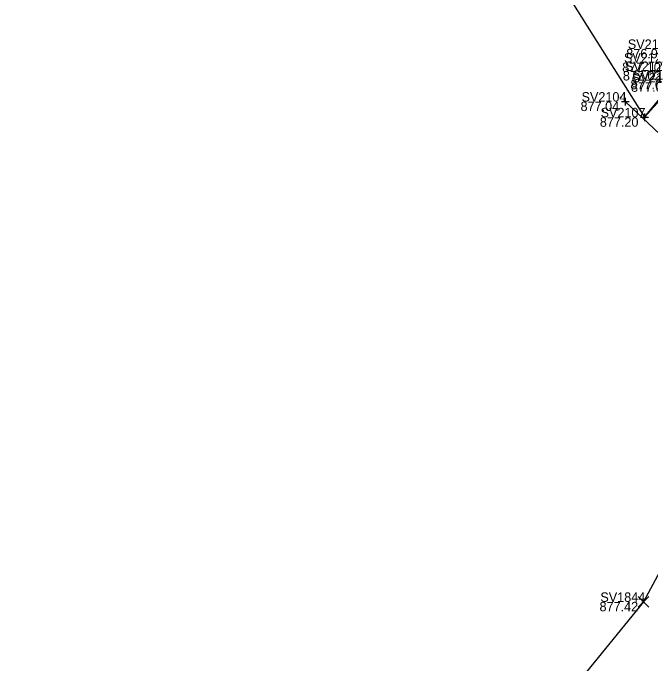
# Model space of a CAD drawing. Extents: x 1475918 to 1480402, y 379235 to 383359.
# Drawn here: x 1480006.1 to 1480087.1, y 379351.5 to 379434.1 of the extents above; entities that cross this region are included whole.
import ezdxf

# ---------------------------------------------------------------- set-up
doc = ezdxf.new("R2010")
doc.units = 0
for name, color, linetype in [('BD_X_Building', 7, 'Continuous'), ('BD_X_Porch_or_Deck', 7, 'Continuous'), ('SV_X_Random_Point', 7, 'Continuous'), ('SV_X_Shot_Marker', 7, 'Continuous'), ('SV_X_Text_Comment', 7, 'Continuous'), ('SV_X_Text_Elevation', 7, 'Continuous'), ('SV_X_Text_Name', 7, 'Continuous'), ('XS_X_Ground_Line', 7, 'Continuous')]:
    doc.layers.add(name, color=color, linetype=linetype)

msp = doc.modelspace()

# ---------------------------------------------------------------- linework, layer by layer
at = {"layer": 'BD_X_Building'}
msp.add_line((1480104.802, 379403.171), (1480083.928, 379422.85), dxfattribs=at)
at = {"layer": 'BD_X_Porch_or_Deck'}
msp.add_lwpolyline([(1480086.359, 379420.856), (1480090.342, 379425.296), (1480106.828, 379410.03), (1480102.697, 379405.586)], dxfattribs=at)
at = {"layer": 'SV_X_Random_Point'}
for p, q in [((1480085.569, 379358.641), (1480086.903, 379359.976)), ((1480085.569, 379359.976), (1480086.903, 379358.641))]:
    msp.add_line(p, q, dxfattribs=at)
at = {"layer": 'SV_X_Shot_Marker'}
for p, q in [((1480083.351, 379423.394), (1480083.315, 379423.428)), ((1480083.316, 379423.393), (1480083.35, 379423.429)), ((1480083.333, 379423.411), (1480083.333, 379423.411)), ((1480083.928, 379423.35), (1480083.928, 379422.35)), ((1480083.428, 379422.85), (1480084.428, 379422.85)), ((1480083.928, 379422.85), (1480083.928, 379422.85)), ((1480085.859, 379420.856), (1480086.859, 379420.856)), ((1480086.34, 379420.873), (1480086.378, 379420.84)), ((1480086.342, 379420.838), (1480086.376, 379420.875)), ((1480086.359, 379421.356), (1480086.359, 379420.356)), ((1480086.359, 379420.856), (1480086.359, 379420.856)), ((1480086.359, 379420.856), (1480086.359, 379420.856))]:
    msp.add_line(p, q, dxfattribs=at)
at = {"layer": 'XS_X_Ground_Line'}
msp.add_lwpolyline([(1480006.1, 379539.863), (1480007.842, 379531.628), (1480033.67, 379508.294), (1480057.214, 379467.144), (1480086.359, 379420.856), (1480090.594, 379425.98), (1480107.187, 379411.187), (1480107.453, 379402.373), (1480102.088, 379388.747), (1480086.236, 379359.309), (1480073.607, 379343.82), (1480050.568, 379305.437), (1480035.484, 379289.224), (1480038.409, 379286.458), (1480058.546, 379269.388), (1480107.531, 379298.913), (1480122.138, 379319.279), (1480155.681, 379356.134), (1480185.507, 379331.81), (1480220.406, 379306.568), (1480244.129, 379283.073)], dxfattribs=at)

# ---------------------------------------------------------------- texts
at = {"layer": 'SV_X_Text_Comment'}
for s, p in [('BLD1', (1480083.333, 379423.351)), ('POR1', (1480086.359, 379420.796))]:
    msp.add_text(s, height=0.06, dxfattribs=at).set_placement(p)
at = {"layer": 'SV_X_Text_Elevation'}
for s, height, p in [('876.90', 1.2, (1480084.047, 379428.347)), ('877.10', 1.2, (1480083.528, 379426.607)), ('877.02', 1.2, (1480083.618, 379425.537)), ('877.05', 1.2, (1480084.572, 379424.42)), ('877.02', 1.2, (1480084.654, 379424.096)), ('876.8940', 0.06, (1480082.941, 379423.351)), ('877.04', 1.2, (1480078.24, 379421.65)), ('877.04', 0.06, (1480083.644, 379422.79)), ('877.20', 1.2, (1480080.69, 379419.656)), ('877.2036', 0.06, (1480085.966, 379420.796)), ('877.20', 0.06, (1480086.076, 379420.796)), ('877.42', 1.2, (1480080.652, 379358.109)), ('877.42', 0.06, (1480085.957, 379359.249))]:
    msp.add_text(s, height=height, dxfattribs=at).set_placement(p)
at = {"layer": 'SV_X_Text_Name'}
for s, height, p in [('SV2120', 1.2, (1480084.247, 379429.547)), ('SV2121', 1.2, (1480083.753, 379427.807)), ('SV2122', 1.2, (1480083.874, 379426.737)), ('SV2108', 1.2, (1480084.759, 379425.296)), ('SV2123', 1.2, (1480084.828, 379425.62)), ('SV2104', 1.2, (1480078.364, 379422.85)), ('SV2104', 0.06, (1480083.055, 379423.411)), ('SV2104', 0.06, (1480083.65, 379422.85)), ('SV2107', 1.2, (1480080.785, 379420.856)), ('SV2107', 0.06, (1480086.08, 379420.856)), ('SV2107', 0.06, (1480086.08, 379420.856)), ('SV1844', 1.2, (1480080.757, 379359.309)), ('SV1844', 0.06, (1480085.962, 379359.309))]:
    msp.add_text(s, height=height, dxfattribs=at).set_placement(p)

doc.saveas('drawing.dxf')
